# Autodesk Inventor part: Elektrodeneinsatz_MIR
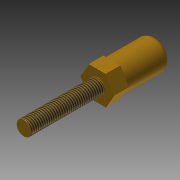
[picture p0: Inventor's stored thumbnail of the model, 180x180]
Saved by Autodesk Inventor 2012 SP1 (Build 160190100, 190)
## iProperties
Created: 2012-10
Part Number: Elektrodeneinsatz_MIR
Material: Default
Document SubType Name: Modeling
Designer: Dominic Mähling
Density: 1 g/cm^3
Author: Dominic Mähling
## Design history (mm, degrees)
derived "Elektrodeneinsatz.ipt"
feature "Volumenkörper1::Elektrodeneinsatz.ipt" dims "d0" = 10
tag "Bezeichnung1"
node "Volumenkörper1"
